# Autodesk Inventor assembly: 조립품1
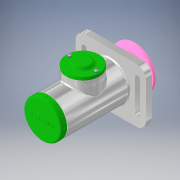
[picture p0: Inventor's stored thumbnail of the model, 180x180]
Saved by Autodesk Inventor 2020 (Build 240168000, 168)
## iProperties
Created: 2021-07
Part Number: 조립품1
Document SubType Name: Assembly
Designer: MIRAE
Author: MIRAE
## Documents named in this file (20)
- C:\Users\MIRAE\Desktop\710706V1028\조립품1.iam
- C:\Users\MIRAE\Desktop\710706V1028\본체.ipt
- C:\Users\MIRAE\Desktop\710706V1028\V-벨트풀리.ipt
- C:\Users\MIRAE\Desktop\710706V1028\너트 M10.ipt
- C:\Users\MIRAE\Desktop\710706V1028\멈춤링 15 x 1.ipt
- C:\Users\MIRAE\Desktop\710706V1028\멈춤링 35 x 1.6.ipt
- C:\Users\MIRAE\Desktop\710706V1028\베어링 15 x 35 x 11.ipt
- C:\Users\MIRAE\Desktop\710706V1028\볼트 M4 x 10.ipt
- C:\Users\MIRAE\Desktop\710706V1028\부시1.ipt
- C:\Users\MIRAE\Desktop\710706V1028\부시2.ipt
- C:\Users\MIRAE\Desktop\710706V1028\사이드 커버.ipt
- 사이드 커버.ipt
- C:\Users\MIRAE\Desktop\710706V1028\십자볼트 M3 x 10.ipt
- C:\Users\MIRAE\Desktop\710706V1028\오일 실 15 25 7.ipt
- C:\Users\MIRAE\Desktop\710706V1028\와셔 3 x 6.ipt
- C:\Users\MIRAE\Desktop\710706V1028\와셔 4 x 16.ipt
- C:\Users\MIRAE\Desktop\710706V1028\와셔 10 x 21.ipt
- C:\Users\MIRAE\Desktop\710706V1028\축.ipt
- C:\Users\MIRAE\Desktop\710706V1028\키 4 x 4 x 18.ipt
- C:\Users\MIRAE\Desktop\710706V1028\탑 커버.ipt
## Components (2 placed, 2 different names)
1. V-벨트풀리:1
2. ISO 4017 M4 x 10:1 — 각도:3
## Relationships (1: Angle 1)
- 각도:3 [Angle]: ISO 4017 M4 x 10:1
